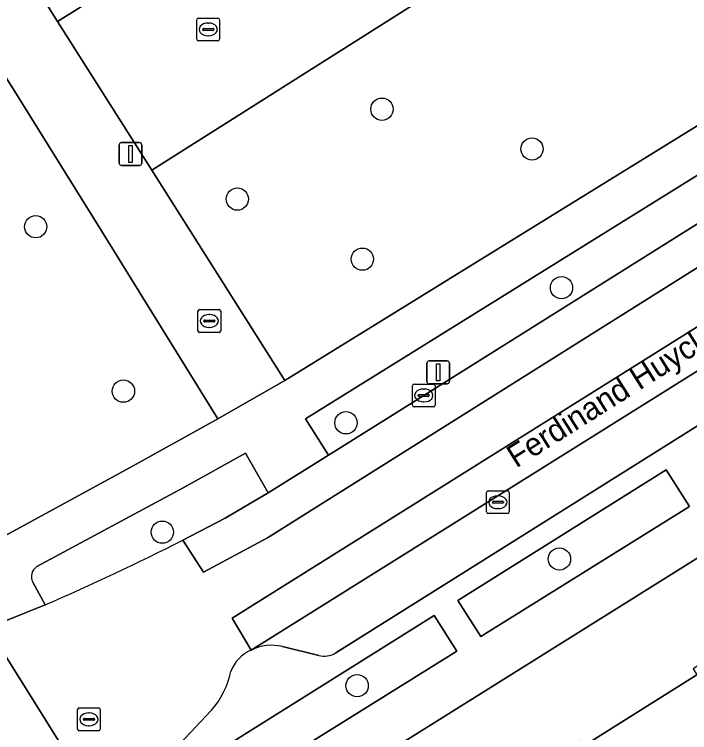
# Model space of a CAD drawing. Extents: x 160077 to 160948, y 386481 to 387498.
# Drawn here: x 160412.59 to 160442.23, y 386874.51 to 386906.01 of the extents above; entities that cross this region are included whole.
import ezdxf

# ---------------------------------------------------------------- set-up
doc = ezdxf.new("R2010")
doc.units = 0
for name, color, linetype in [('IMGEO_Boom', 7, 'Continuous'), ('IMGEO_Brandkraan', 7, 'Continuous'), ('IMGEO_Erf', 7, 'Continuous'), ('IMGEO_Groenvoorziening', 7, 'Continuous'), ('IMGEO_Kolk', 7, 'Continuous'), ('IMGEO_Lichtmast', 7, 'Continuous'), ('IMGEO_Openbare_ruimte_label', 7, 'Continuous'), ('IMGEO_Pand', 7, 'Continuous'), ('IMGEO_Parkeervlak_open', 7, 'Continuous'), ('IMGEO_Rijbaan_lokaal_gesloten', 7, 'Continuous'), ('IMGEO_Rijbaan_lokaal_open', 7, 'Continuous'), ('IMGEO_Rioolput', 7, 'Continuous'), ('IMGEO_Voetpad_open', 7, 'Continuous')]:
    doc.layers.add(name, color=color, linetype=linetype)

msp = doc.modelspace()

# ---------------------------------------------------------------- linework, layer by layer
at = {"layer": 'IMGEO_Boom'}
for centre in [(160428.721, 386901.854), (160435.311, 386900.11), (160422.376, 386897.911), (160413.525, 386896.698), (160427.863, 386895.276), (160436.602, 386894.023), (160417.375, 386889.487), (160427.141, 386888.098), (160419.081, 386883.301), (160436.512, 386882.124), (160427.633, 386876.567)]:
    msp.add_circle(centre, 0.489, dxfattribs=at)
at = {"layer": 'IMGEO_Brandkraan'}
for p, q in [((160420.644, 386892.138), (160420.644, 386892.99)), ((160420.719, 386893.064), (160421.571, 386893.064)), ((160421.645, 386892.99), (160421.645, 386892.138)), ((160421.132, 386892.844), (160421.157, 386892.844)), ((160420.903, 386892.558), (160420.903, 386892.57)), ((160421.341, 386892.521), (160420.943, 386892.521)), ((160420.946, 386892.607), (160421.344, 386892.607)), ((160421.387, 386892.57), (160421.387, 386892.558)), ((160421.571, 386892.064), (160420.719, 386892.064)), ((160421.155, 386892.284), (160421.13, 386892.284))]:
    msp.add_line(p, q, dxfattribs=at)
for points in [[(160420.644, 386892.138), (160420.644, 386892.99)], [(160420.719, 386893.064), (160421.571, 386893.064)], [(160421.645, 386892.99), (160421.645, 386892.138)], [(160421.571, 386892.064), (160420.719, 386892.064)]]:
    msp.add_lwpolyline(points, dxfattribs=at)
for centre, radius, start, end in [((160420.721, 386892.988), 0.0765, 91.552, 178.448), ((160420.721, 386892.988), 0.0765, 91.552, 178.448), ((160421.569, 386892.988), 0.0765, 1.552, 88.448), ((160421.569, 386892.988), 0.0765, 1.552, 88.448), ((160420.943, 386892.567), 0.0403, 85.8775, 175.7526), ((160420.94, 386892.557), 0.0366, 178.938, 274.7102), ((160421.344, 386892.564), 0.043, 264.8664, 352.4533), ((160421.348, 386892.569), 0.0386, 1.7309, 96.639), ((160420.721, 386892.14), 0.0765, 181.552, 268.448), ((160420.721, 386892.14), 0.0765, 181.552, 268.448), ((160421.569, 386892.14), 0.0765, 271.552, 358.448), ((160421.569, 386892.14), 0.0765, 271.552, 358.448)]:
    msp.add_arc(centre, radius, start, end, dxfattribs=at)
for centre, major_axis, ratio, start_param, end_param in [((160421.131, 386892.564), (-0.387, 0.002), 0.722429, 4.712389, 7.853982), ((160421.156, 386892.564), (-0.39, 0.002), 0.717154, 1.570796, 4.712389)]:
    msp.add_ellipse(centre, major_axis=major_axis, ratio=ratio, start_param=start_param, end_param=end_param, dxfattribs=at)
at = {"layer": 'IMGEO_Erf'}
msp.add_lwpolyline([(160500, 386918.098), (160419.904, 386867.997), (160419.331, 386867.627), (160421.508, 386864.204), (160421.78, 386864.376), (160421.953, 386864.101), (160426.888, 386867.213), (160426.715, 386867.487), (160426.949, 386867.634), (160427.149, 386867.317), (160432.16, 386870.477), (160431.953, 386870.806), (160432.147, 386870.927), (160432.223, 386870.974), (160432.43, 386870.642), (160437.271, 386873.702), (160437.08, 386874.008), (160437.359, 386874.184), (160437.543, 386873.893), (160442.548, 386877.05)], dxfattribs=at)
at = {"layer": 'IMGEO_Groenvoorziening'}
for points in [[(160409.893, 386881.917), (160411.377, 386882.716), (160417.798, 386886.204), (160421.525, 386888.269), (160416.406, 386896.516), (160412.535, 386902.752), (160408.864, 386908.506), (160403.038, 386917.636), (160399.533, 386923.281), (160396.796, 386927.687), (160394.729, 386930.878), (160392.284, 386934.918), (160389.939, 386938.794), (160387.823, 386942.091)], [(160450.499, 386908.528), (160449.013, 386911.065), (160445.701, 386916.313), (160418.626, 386899.176), (160424.466, 386889.949), (160450.017, 386905.729)], [(160423.735, 386885.033), (160422.733, 386886.769), (160420.003, 386885.249), (160413.576, 386881.791)], [(160419.976, 386882.948), (160421.837, 386883.922), (160423.735, 386885.033)], [(160413.4, 386881.105), (160413.94, 386880.112)], [(160432.012, 386878.087), (160431.019, 386879.651), (160422.186, 386874.126), (160417.76, 386870.362)], [(160418.233, 386869.493), (160432.012, 386878.087)]]:
    msp.add_lwpolyline(points, dxfattribs=at)
for points in [[(160414.476, 386905.699), (160419.644, 386908.926), (160416.321, 386914.248), (160411.153, 386911.02)], [(160453.275, 386903.561), (160452.383, 386905.061), (160425.369, 386888.267), (160426.372, 386886.679), (160430.557, 386889.297), (160447.876, 386900.154)], [(160442.215, 386884.428), (160441.198, 386886.032), (160432.048, 386880.31), (160433.056, 386878.721)]]:
    msp.add_lwpolyline(points, close=True, dxfattribs=at)
for centre, radius, start, end in [((160369.624, 386982.274), 111.36, 293.45046, 296.88228), ((160413.851, 386881.355), 0.515, 122.2065, 209.0146)]:
    msp.add_arc(centre, radius, start, end, dxfattribs=at)
at = {"layer": 'IMGEO_Kolk'}
for p, q in [((160420.595, 386904.926), (160420.595, 386905.778)), ((160420.67, 386905.852), (160421.522, 386905.852)), ((160421.083, 386905.632), (160421.108, 386905.632)), ((160421.596, 386905.778), (160421.596, 386904.926)), ((160420.854, 386905.346), (160420.854, 386905.358)), ((160421.292, 386905.309), (160420.894, 386905.309)), ((160420.897, 386905.395), (160421.295, 386905.395)), ((160421.338, 386905.358), (160421.338, 386905.346)), ((160421.106, 386905.072), (160421.081, 386905.072)), ((160421.522, 386904.852), (160420.67, 386904.852)), ((160430.131, 386889.797), (160430.983, 386889.797)), ((160430.056, 386888.871), (160430.056, 386889.723)), ((160430.544, 386889.577), (160430.569, 386889.577)), ((160431.057, 386889.723), (160431.057, 386888.871)), ((160430.315, 386889.291), (160430.315, 386889.303)), ((160430.753, 386889.254), (160430.355, 386889.254)), ((160430.358, 386889.34), (160430.756, 386889.34)), ((160430.799, 386889.303), (160430.799, 386889.291)), ((160430.567, 386889.017), (160430.542, 386889.017)), ((160430.983, 386888.797), (160430.131, 386888.797)), ((160433.386, 386885.115), (160434.238, 386885.115)), ((160433.311, 386884.189), (160433.311, 386885.041)), ((160433.799, 386884.895), (160433.824, 386884.895)), ((160434.312, 386885.041), (160434.312, 386884.189)), ((160433.57, 386884.609), (160433.57, 386884.621)), ((160434.008, 386884.572), (160433.61, 386884.572)), ((160433.613, 386884.658), (160434.011, 386884.658)), ((160434.054, 386884.621), (160434.054, 386884.609)), ((160433.822, 386884.335), (160433.797, 386884.335)), ((160434.238, 386884.115), (160433.386, 386884.115))]:
    msp.add_line(p, q, dxfattribs=at)
for points in [[(160420.595, 386904.926), (160420.595, 386905.778)], [(160420.67, 386905.852), (160421.522, 386905.852)], [(160421.596, 386905.778), (160421.596, 386904.926)], [(160421.522, 386904.852), (160420.67, 386904.852)], [(160430.131, 386889.797), (160430.983, 386889.797)], [(160430.056, 386888.871), (160430.056, 386889.723)], [(160431.057, 386889.723), (160431.057, 386888.871)], [(160430.983, 386888.797), (160430.131, 386888.797)], [(160433.386, 386885.115), (160434.238, 386885.115)], [(160433.311, 386884.189), (160433.311, 386885.041)], [(160434.312, 386885.041), (160434.312, 386884.189)], [(160434.238, 386884.115), (160433.386, 386884.115)]]:
    msp.add_lwpolyline(points, dxfattribs=at)
for centre, radius, start, end in [((160420.672, 386905.776), 0.0765, 91.552, 178.448), ((160420.672, 386905.776), 0.0765, 91.552, 178.448), ((160421.52, 386905.776), 0.0765, 1.552, 88.448), ((160421.52, 386905.776), 0.0765, 1.552, 88.448), ((160420.894, 386905.355), 0.0403, 85.8775, 175.7526), ((160420.891, 386905.345), 0.0366, 178.938, 274.7102), ((160421.295, 386905.352), 0.043, 264.8664, 352.4533), ((160421.299, 386905.357), 0.0386, 1.7309, 96.639), ((160420.672, 386904.928), 0.0765, 181.552, 268.448), ((160420.672, 386904.928), 0.0765, 181.552, 268.448), ((160421.52, 386904.928), 0.0765, 271.552, 358.448), ((160421.52, 386904.928), 0.0765, 271.552, 358.448), ((160430.133, 386889.721), 0.0765, 91.552, 178.448), ((160430.133, 386889.721), 0.0765, 91.552, 178.448), ((160430.981, 386889.721), 0.0765, 1.552, 88.448), ((160430.981, 386889.721), 0.0765, 1.552, 88.448), ((160430.355, 386889.3), 0.0403, 85.8775, 175.7526), ((160430.352, 386889.29), 0.0366, 178.938, 274.7102), ((160430.756, 386889.297), 0.043, 264.8664, 352.4533), ((160430.76, 386889.302), 0.0386, 1.7309, 96.639), ((160430.133, 386888.873), 0.0765, 181.552, 268.448), ((160430.133, 386888.873), 0.0765, 181.552, 268.448), ((160430.981, 386888.873), 0.0765, 271.552, 358.448), ((160430.981, 386888.873), 0.0765, 271.552, 358.448), ((160433.388, 386885.039), 0.0765, 91.552, 178.448), ((160433.388, 386885.039), 0.0765, 91.552, 178.448), ((160434.236, 386885.039), 0.0765, 1.552, 88.448), ((160434.236, 386885.039), 0.0765, 1.552, 88.448), ((160433.61, 386884.618), 0.0403, 85.8775, 175.7526), ((160433.607, 386884.608), 0.0366, 178.938, 274.7102), ((160434.011, 386884.615), 0.043, 264.8664, 352.4533), ((160434.015, 386884.62), 0.0386, 1.7309, 96.639), ((160433.388, 386884.191), 0.0765, 181.552, 268.448), ((160433.388, 386884.191), 0.0765, 181.552, 268.448), ((160434.236, 386884.191), 0.0765, 271.552, 358.448), ((160434.236, 386884.191), 0.0765, 271.552, 358.448)]:
    msp.add_arc(centre, radius, start, end, dxfattribs=at)
for centre, major_axis, ratio, start_param, end_param in [((160421.082, 386905.352), (-0.387, 0.002), 0.722429, 4.712389, 7.853982), ((160421.107, 386905.352), (-0.39, 0.002), 0.717154, 1.570796, 4.712389), ((160430.543, 386889.297), (-0.387, 0.002), 0.722429, 4.712389, 7.853982), ((160430.568, 386889.297), (-0.39, 0.002), 0.717154, 1.570796, 4.712389), ((160433.798, 386884.615), (-0.387, 0.002), 0.722429, 4.712389, 7.853982), ((160433.823, 386884.615), (-0.39, 0.002), 0.717154, 1.570796, 4.712389)]:
    msp.add_ellipse(centre, major_axis=major_axis, ratio=ratio, start_param=start_param, end_param=end_param, dxfattribs=at)
at = {"layer": 'IMGEO_Lichtmast'}
for p, q in [((160417.191, 386899.486), (160417.191, 386900.286)), ((160417.191, 386900.286), (160417.191, 386899.486)), ((160417.291, 386900.386), (160418.081, 386900.386)), ((160418.081, 386900.386), (160417.291, 386900.386)), ((160418.181, 386900.286), (160418.181, 386899.486)), ((160418.181, 386899.486), (160418.181, 386900.286)), ((160418.081, 386899.386), (160417.291, 386899.386)), ((160417.291, 386899.386), (160418.081, 386899.386)), ((160430.793, 386890.812), (160431.583, 386890.812)), ((160431.583, 386890.812), (160430.793, 386890.812)), ((160430.693, 386889.912), (160430.693, 386890.712)), ((160430.693, 386890.712), (160430.693, 386889.912)), ((160431.683, 386890.712), (160431.683, 386889.912)), ((160431.683, 386889.912), (160431.683, 386890.712)), ((160431.583, 386889.812), (160430.793, 386889.812)), ((160430.793, 386889.812), (160431.583, 386889.812))]:
    msp.add_line(p, q, dxfattribs=at)
for points in [[(160417.611, 386900.261), (160417.761, 386900.261), (160417.761, 386899.511), (160417.611, 386899.511), (160417.611, 386900.261)], [(160431.113, 386890.687), (160431.263, 386890.687), (160431.263, 386889.937), (160431.113, 386889.937), (160431.113, 386890.687)]]:
    msp.add_lwpolyline(points, dxfattribs=at)
for centre, start, end in [((160417.291, 386900.286), 90, 180), ((160417.291, 386900.286), 90, 180), ((160418.081, 386900.286), 0, 90), ((160418.081, 386900.286), 360, 90), ((160417.291, 386899.486), 180, 270), ((160417.291, 386899.486), 180, 270), ((160418.081, 386899.486), 270, 0), ((160418.081, 386899.486), 270, 0), ((160430.793, 386890.712), 90, 180), ((160430.793, 386890.712), 90, 180), ((160431.583, 386890.712), 0, 90), ((160431.583, 386890.712), 360, 90), ((160430.793, 386889.912), 180, 270), ((160430.793, 386889.912), 180, 270), ((160431.583, 386889.912), 270, 0), ((160431.583, 386889.912), 270, 0)]:
    msp.add_arc(centre, 0.1, start, end, dxfattribs=at)
at = {"layer": 'IMGEO_Pand'}
msp.add_lwpolyline([(160442.592, 386877.433), (160442.388, 386877.304), (160442.548, 386877.05), (160437.543, 386873.893), (160441.594, 386867.488), (160446.465, 386870.563), (160446.797, 386870.772)], close=True, dxfattribs=at)
at = {"layer": 'IMGEO_Parkeervlak_open'}
for points in [[(160498.541, 386925.423), (160471.132, 386908.242), (160422.979, 386878.128)], [(160426.691, 386878.004), (160472.2, 386906.553), (160496.977, 386922.083)], [(160424.352, 386878.287), (160425.949, 386877.889)]]:
    msp.add_lwpolyline(points, dxfattribs=at)
for centre, radius, start, end in [((160423.89, 386876.27), 2.069, 77.0918, 116.1196), ((160426.186, 386878.809), 0.95, 255.5424, 302.0775)]:
    msp.add_arc(centre, radius, start, end, dxfattribs=at)
at = {"layer": 'IMGEO_Rijbaan_lokaal_gesloten'}
for points in [[(160498.016, 386929.634), (160497.139, 386931.045), (160496.096, 386930.398), (160483.867, 386922.752), (160482.819, 386922.137), (160481.635, 386921.351), (160463.505, 386909.997), (160455.879, 386905.184), (160453.275, 386903.561), (160447.876, 386900.154), (160430.557, 386889.297), (160426.372, 386886.679), (160423.735, 386885.033), (160421.837, 386883.922), (160419.976, 386882.948), (160420.887, 386881.55), (160423.695, 386883.049), (160454.149, 386902.178)], [(160498.541, 386925.423), (160498.836, 386925.601), (160500.056, 386926.398), (160499.173, 386927.789), (160470.277, 386909.673), (160422.153, 386879.524), (160422.979, 386878.128), (160471.132, 386908.242)]]:
    msp.add_lwpolyline(points, close=True, dxfattribs=at)
msp.add_lwpolyline([(160399.264, 386859.036), (160399.298, 386859.084), (160399.478, 386859.209), (160404.134, 386862.447), (160416.702, 386870.665), (160411.413, 386879.123)], dxfattribs=at)
at = {"layer": 'IMGEO_Rijbaan_lokaal_open'}
for points in [[(160387.906, 386960.997), (160388.955, 386959.055), (160390.263, 386956.936), (160402.32, 386937.614), (160416.924, 386914.647), (160416.321, 386914.248), (160419.644, 386908.926), (160414.476, 386905.699), (160418.626, 386899.176), (160445.701, 386916.313), (160441.379, 386922.838), (160437.094, 386920.111), (160426.867, 386913.603), (160423.535, 386918.746), (160421.339, 386917.461), (160407.72, 386939.3), (160394.157, 386960.926)], [(160422.979, 386878.128), (160422.153, 386879.524), (160470.277, 386909.673), (160499.173, 386927.789), (160498.016, 386929.634), (160454.149, 386902.178), (160423.695, 386883.049), (160420.887, 386881.55), (160419.976, 386882.948)], [(160413.94, 386880.112), (160411.64, 386879.199), (160411.413, 386879.123), (160416.702, 386870.665), (160421.228, 386875.484)]]:
    msp.add_lwpolyline(points, dxfattribs=at)
for centre, radius, start, end in [((160369.624, 386982.274), 111.36, 293.45046, 296.88228), ((160423.627, 386876.624), 1.638, 113.3148, 159.994), ((160418.55, 386877.906), 3.611, 317.8708, 348.4611)]:
    msp.add_arc(centre, radius, start, end, dxfattribs=at)
at = {"layer": 'IMGEO_Rioolput'}
for p, q in [((160415.36, 386874.665), (160415.36, 386875.517)), ((160415.435, 386875.591), (160416.287, 386875.591)), ((160415.848, 386875.371), (160415.873, 386875.371)), ((160416.361, 386875.517), (160416.361, 386874.665)), ((160415.619, 386875.085), (160415.619, 386875.097)), ((160416.057, 386875.048), (160415.659, 386875.048)), ((160415.662, 386875.134), (160416.06, 386875.134)), ((160416.103, 386875.097), (160416.103, 386875.085)), ((160415.871, 386874.811), (160415.846, 386874.811)), ((160416.287, 386874.591), (160415.435, 386874.591))]:
    msp.add_line(p, q, dxfattribs=at)
for points in [[(160415.36, 386874.665), (160415.36, 386875.517)], [(160415.435, 386875.591), (160416.287, 386875.591)], [(160416.361, 386875.517), (160416.361, 386874.665)], [(160416.287, 386874.591), (160415.435, 386874.591)]]:
    msp.add_lwpolyline(points, dxfattribs=at)
for centre, radius, start, end in [((160415.437, 386875.515), 0.0765, 91.552, 178.448), ((160415.437, 386875.515), 0.0765, 91.552, 178.448), ((160416.285, 386875.515), 0.0765, 1.552, 88.448), ((160416.285, 386875.515), 0.0765, 1.552, 88.448), ((160415.659, 386875.094), 0.0403, 85.8775, 175.7526), ((160415.656, 386875.084), 0.0366, 178.938, 274.7102), ((160416.06, 386875.091), 0.043, 264.8664, 352.4533), ((160416.064, 386875.096), 0.0386, 1.7309, 96.639), ((160415.437, 386874.667), 0.0765, 181.552, 268.448), ((160415.437, 386874.667), 0.0765, 181.552, 268.448), ((160416.285, 386874.667), 0.0765, 271.552, 358.448), ((160416.285, 386874.667), 0.0765, 271.552, 358.448)]:
    msp.add_arc(centre, radius, start, end, dxfattribs=at)
for centre, major_axis, ratio, start_param, end_param in [((160415.847, 386875.091), (-0.387, 0.002), 0.722429, 4.712389, 7.853982), ((160415.872, 386875.091), (-0.39, 0.002), 0.717154, 1.570796, 4.712389)]:
    msp.add_ellipse(centre, major_axis=major_axis, ratio=ratio, start_param=start_param, end_param=end_param, dxfattribs=at)
at = {"layer": 'IMGEO_Voetpad_open'}
for points in [[(160414.476, 386905.699), (160411.153, 386911.02), (160390.688, 386943.438), (160387.728, 386942.238), (160387.823, 386942.091), (160389.939, 386938.794), (160392.284, 386934.918), (160394.729, 386930.878), (160396.796, 386927.687), (160399.533, 386923.281), (160403.038, 386917.636), (160408.864, 386908.506), (160412.535, 386902.752), (160416.406, 386896.516), (160421.525, 386888.269), (160424.466, 386889.949), (160418.626, 386899.176)], [(160442.215, 386884.428), (160433.056, 386878.721), (160432.048, 386880.31), (160441.198, 386886.032)]]:
    msp.add_lwpolyline(points, close=True, dxfattribs=at)
for points in [[(160494.293, 386933.466), (160473.286, 386920.304), (160472.105, 386919.565), (160450.017, 386905.729), (160424.466, 386889.949), (160421.525, 386888.269), (160417.798, 386886.204), (160411.377, 386882.716), (160409.893, 386881.917)], [(160496.977, 386922.083), (160472.2, 386906.553), (160426.691, 386878.004)], [(160404.564, 386850.02), (160407.136, 386853.435), (160407.802, 386854.32), (160411.259, 386858.909), (160412.23, 386860.189), (160415.215, 386864.126), (160416.466, 386865.776), (160419.331, 386867.627), (160419.904, 386867.997), (160500, 386918.098), (160503.979, 386920.59)], [(160413.576, 386881.791), (160420.003, 386885.249), (160422.733, 386886.769), (160423.735, 386885.033), (160426.372, 386886.679), (160425.369, 386888.267), (160452.383, 386905.061)], [(160408.572, 386878.179), (160411.413, 386879.123), (160411.64, 386879.199), (160413.94, 386880.112), (160413.4, 386881.105)], [(160417.76, 386870.362), (160422.186, 386874.126), (160431.019, 386879.651), (160432.012, 386878.087)], [(160425.949, 386877.889), (160424.352, 386878.287)], [(160432.012, 386878.087), (160418.233, 386869.493)], [(160421.228, 386875.484), (160416.702, 386870.665), (160416.575, 386870.496), (160409.222, 386860.905), (160408.542, 386860.066), (160407.918, 386859.274), (160407.31, 386858.499), (160403.74, 386853.668)]]:
    msp.add_lwpolyline(points, dxfattribs=at)
for centre, radius, start, end in [((160413.851, 386881.355), 0.515, 122.2065, 209.0146), ((160423.89, 386876.27), 2.069, 77.0918, 116.1196), ((160423.627, 386876.624), 1.638, 113.3148, 159.994), ((160426.186, 386878.809), 0.95, 255.5424, 302.0775), ((160418.55, 386877.906), 3.611, 317.8708, 348.4611)]:
    msp.add_arc(centre, radius, start, end, dxfattribs=at)

# ---------------------------------------------------------------- texts
at = {"layer": 'IMGEO_Openbare_ruimte_label'}
msp.add_text('Ferdinand Huyckstraat', height=1, rotation=32.2604, dxfattribs=at).set_placement((160434.612, 386886.093))

doc.saveas('drawing.dxf')
